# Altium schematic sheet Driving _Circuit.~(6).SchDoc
size A4; SheetNumber: 1; SheetTotal: 1; SPICEModelCacheBUJQYFZZ: <root> / <DocumentId>BUJQYFZZ</DocumentId> / </root>
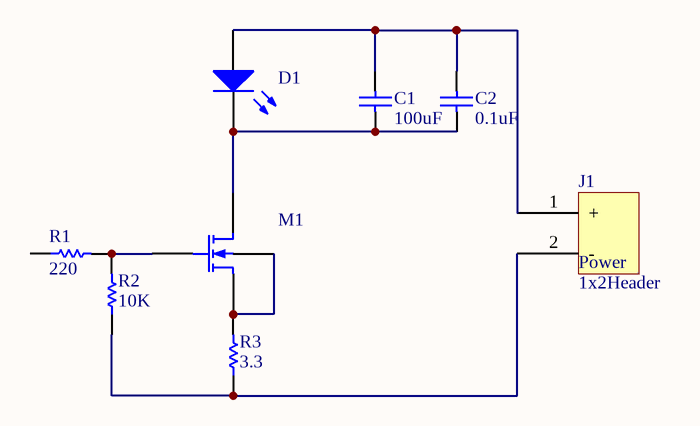
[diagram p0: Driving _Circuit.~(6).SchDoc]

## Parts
C1  value 100uF  (hidden comment: Capacitor)
C2  value 0.1uF  (hidden comment: Capacitor)
D1  Light-Emitting Diode  (value not drawn)
J1  1x2Header
M1  N-channel MOS1 MOSFET Shichman and Hodges Model  (value not drawn)
R1  value 220  (hidden comment: Resistor)
R2  value 10K  (hidden comment: Resistor)
R3  value 3.3  (hidden comment: Resistor)

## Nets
NetC1_1: C1.1 C2.1 D1.2(K) M1.1(D)
NetC1_2: C1.2 C2.2 D1.1(A) J1.1(+)
NetJ1_2: J1.2(-) R2.1 R3.1
NetM1_2: M1.2(G) R1.2 R2.2
NetM1_3: M1.3(S) M1.4(B) R3.2

Not connected (* = marked no-connect by the designer): R1 1

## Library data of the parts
C1 C2 = Capacitor: SimulationGenericComponent: True
D1 = LED: LITEON IR LED; AF: 1; BV: 0; BV_MAX: 1e99; EG: 1.11; FC: 0.5; IBV: 0.001; IS: 1e-14; MJSW: 0.33; NTUN: 30; TNOM: 27; XTI: 3; SimulationGenericComponent: True
M1 = MOSFET N-ch Lev1: IRLZ44N NMOS; CBD: 0; FC: 0.5; IS: 1e-14; KP: 2e-05; PB: 0.8; PHI: 0.6; TNOM: 27; SimulationGenericComponent: True
R1-R3 = Resistor: TC1: 0; SimulationGenericComponent: True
